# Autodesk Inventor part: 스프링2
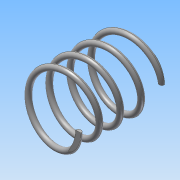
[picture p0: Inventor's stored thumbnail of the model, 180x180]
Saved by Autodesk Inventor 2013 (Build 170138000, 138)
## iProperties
Created: 2014-11
Part Number: 스프링2
Material: 강철, 연강
Document SubType Name: Modeling
Designer: Administrator
Density: 7.86 g/cm^3
Mass: 2.84034 g
Surface Area: 9.76139 cm^2
Volume: 0.361367 cm^3
Author: Administrator
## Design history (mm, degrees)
sketch "스케치1"
  geometry: L1 (0, 0)-(0, 22.913); L2 (0, 22.913)-(8.25, 22.913); L3 (0, 0)-(8.25, 0); C1 r 0.75 at (8.25, 0)
  constraints: 6 end point, 1 centre point, 1 coincident, 1 parallel, 1 perpendicular, 1 vertical
  dimensions: "d0" = 22.91274 distance of L1.start L1.end (derived); "d1" = 8.25 distance of L1.end L2.end; "d2" = 8.25 distance of L1.start L3.end; "d3" = 1.5 diameter of C1
feature "코일1" sketch "스케치1" pitch "d4" = 10; turns "d6" = 4; dims "d5" = 22.91274 (= d0), "d7" = 0, angle "d8" = 90 deg, angle "d9" = 90 deg, "d10" = 0, "d11" = 0
sketch "스케치2"
  geometry: L1 (0, 10)-(22.913, 10); L2 (22.913, 10)-(22.913, -10); L3 (22.913, -10)-(0, -10); L4 (0, -10)-(0, 10); 2 further points
  constraints: 8 end point, 2 parallel, 1 coincident, 1 horizontal, 1 midpoint, 1 perpendicular
  dimensions: "d12" = 22.91274 distance of L1.start L1.end (derived); "d14" = 20 distance of L1.end L2.end
extrude "돌출1" sketch "스케치2" stored distance "d15" = 10; taper "d16" = 0 deg
node "솔리드1"
